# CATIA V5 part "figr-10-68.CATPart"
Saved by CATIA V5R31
Part number: Part1
Bounding box of the stored display mesh (mm): x -80.563 to 63.541, y -72 to 69, z -55 to 6.847
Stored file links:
  D:\PROJECTS\Project 2021\US EDITION\CATIA V5 6R 2021\Resources\Part Files\c10_catia_v5_6r2021_prt\c10_catia_v5_6r2021_prt\figr-10-68.CATPart
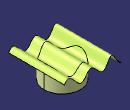
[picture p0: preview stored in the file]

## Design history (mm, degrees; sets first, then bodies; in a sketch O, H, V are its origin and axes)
Set1
  Sketch1 on xy-plane, origin (0, 0, 0), H (-1, 0, 0), V (0, -1, 0)
    circle A1 centre (0, 0) radius 45.985
  Extrude1: Element1 Sketch1, Lim1 56, Lim2 55, Direction xy-plane
  Sketch2 on zx-plane, origin (0, 0, 0), H (1, 0, 0), V (0, 0, -1)
    spline S1 through (-80.5635, 24.8913) (-73.6025, 19.8803) (-54.8525, -3.3629) (-35.1982, 19.8803) (-2.6271, -1.6506) (16.6996, 17.2854) (52.4104, -6.7877) (63.5409, 1.5862)
  Extrude2: Element1 Sketch2, Lim1 72, Lim2 69, Direction Sketch1.V
  Split1: ToCut Extrude1, Cutting Extrude2
Body1 (main body)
